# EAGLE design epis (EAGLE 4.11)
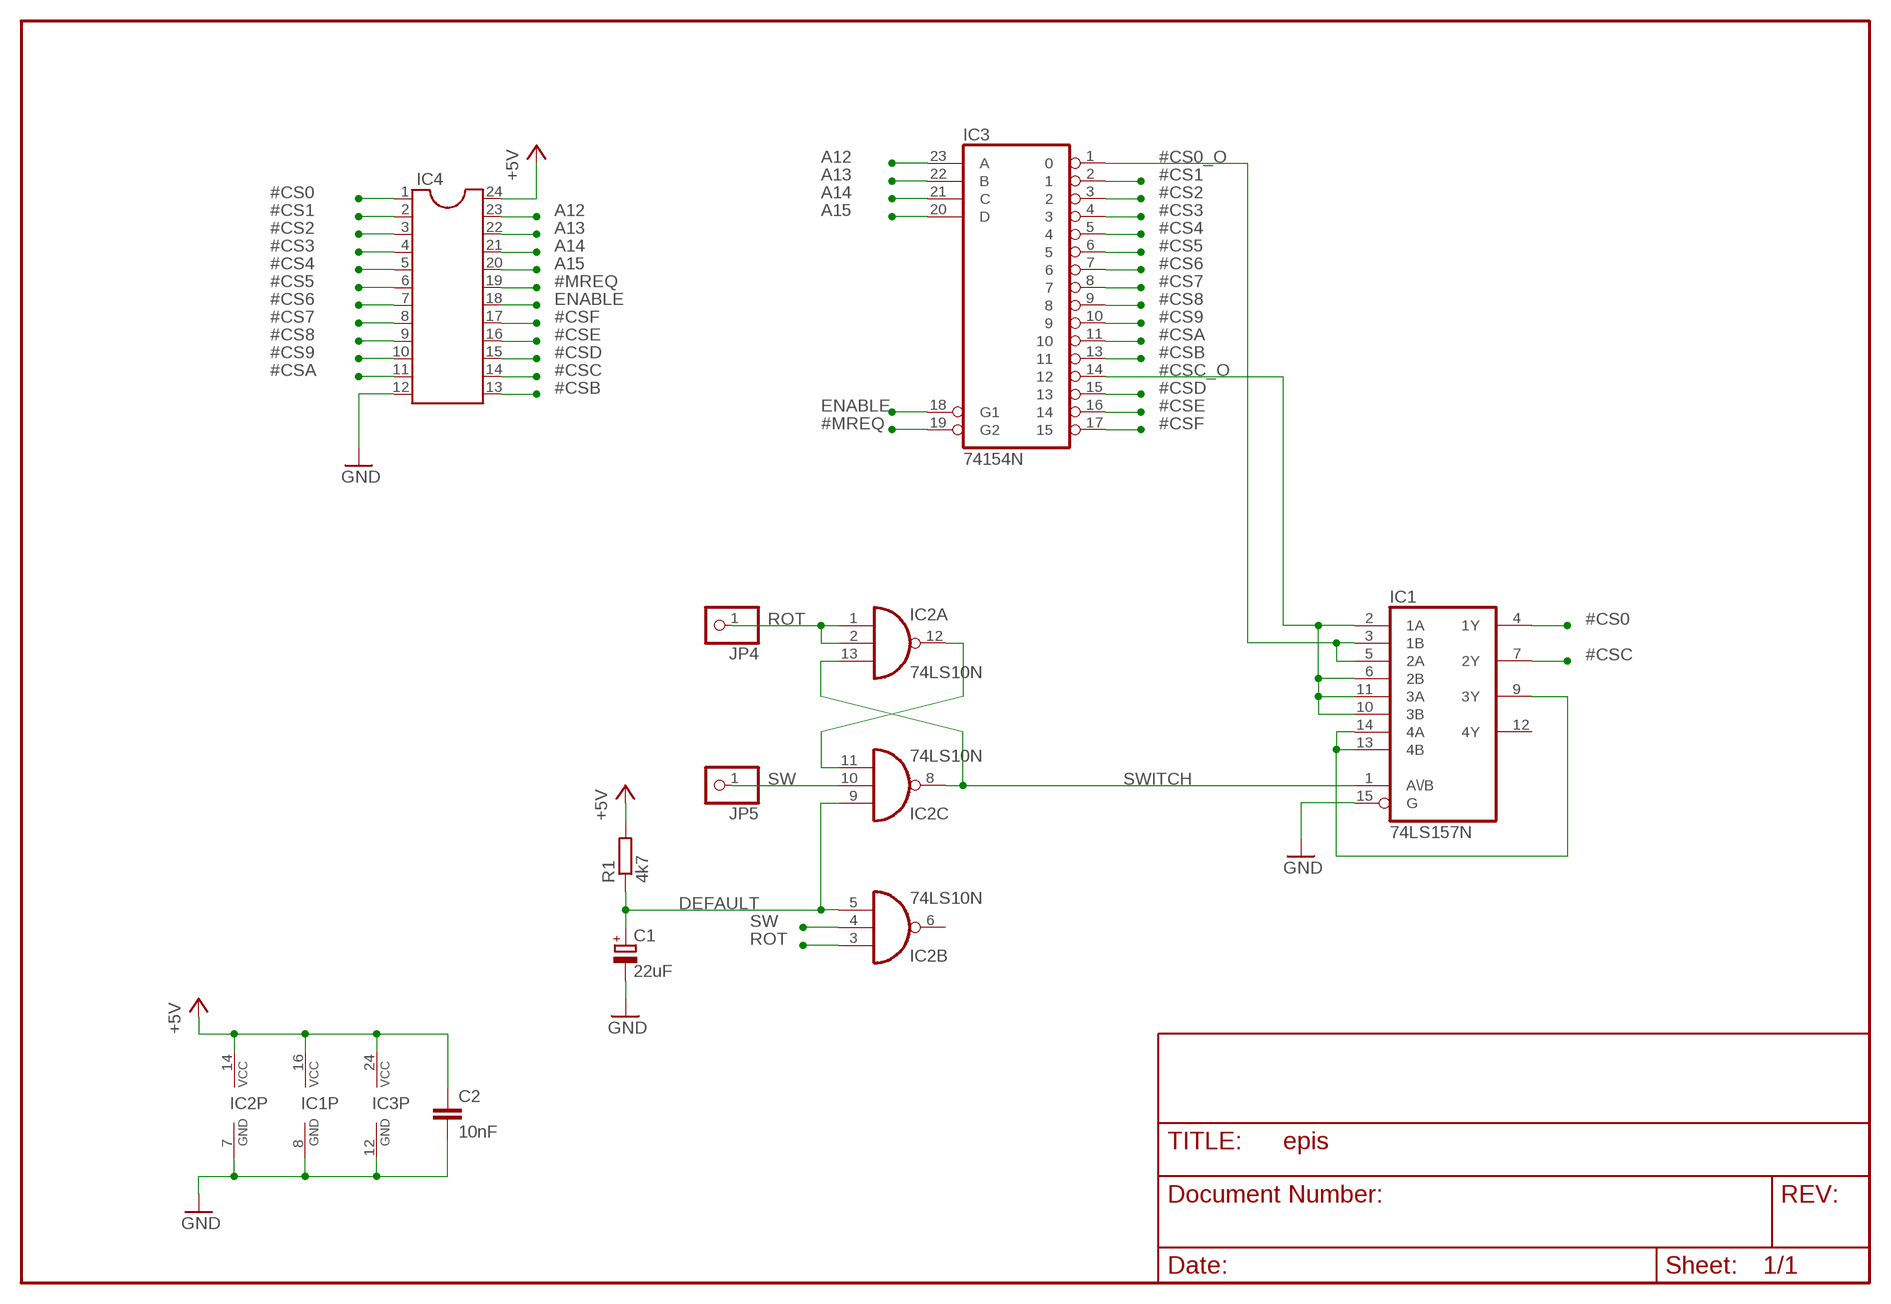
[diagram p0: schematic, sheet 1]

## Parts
C1  22uF  CPOL-EUE5-5  [E5-5]
C2  10nF  C-EU050-024X044  [C050-024X044]
IC1  74LS157N  [DIL16]
IC2  74LS10N  [DIL14]
IC3  74154N  [DIL24-6]
IC4  DIL24-6  [DIL24-6]
JP4  PINHD-1X1  [1X01]
JP5  PINHD-1X1  [1X01]
R1  4k7  R-EU_0309/10  [0309/10]

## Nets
#CS0: IC1.4(1Y) IC4.1
#CS0_O: IC1.3(1B) IC1.5(2A) IC3.1
#CS1: IC3.2 IC4.2
#CS2: IC3.3 IC4.3
#CS3: IC3.4 IC4.4
#CS4: IC3.5 IC4.5
#CS5: IC3.6 IC4.6
#CS6: IC3.7 IC4.7
#CS7: IC3.8 IC4.8
#CS8: IC3.9 IC4.9
#CS9: IC3.10 IC4.10
#CSA: IC3.11 IC4.11
#CSB: IC3.13 IC4.13
#CSC: IC1.7(2Y) IC4.14
#CSC_O: IC1.2(1A) IC1.6(2B) IC1.10(3B) IC1.11(3A) IC3.14
#CSD: IC3.15 IC4.15
#CSE: IC3.16 IC4.16
#CSF: IC3.17 IC4.17
#MREQ: IC3.19(G2) IC4.19
+5V: C2.1 IC1.16(VCC) IC2.14(P:VCC) IC3.24(VCC) IC4.24 R1.2
A12: IC3.23(A) IC4.23
A13: IC3.22(B) IC4.22
A14: IC3.21(C) IC4.21
A15: IC3.20(D) IC4.20
DEFAULT: C1.+ IC2.5(B:I2) IC2.9(C:I0) R1.1
ENABLE: IC3.18(G1) IC4.18
GND: C1.- C2.2 IC1.8(GND) IC1.15(G) IC2.7(P:GND) IC3.12(GND) IC4.12
N$2: IC1.9(3Y) IC1.13(4B) IC1.14(4A)
N$5: IC2.11(C:I2) IC2.12(A:O)
ROT: IC2.1(A:I0) IC2.2(A:I1) IC2.3(B:I0) JP4.1
SW: IC2.4(B:I1) IC2.10(C:I1) JP5.1
SWITCH: IC1.1(A\/B) IC2.8(C:O) IC2.13(A:I2)
Unconnected: IC1.12(4Y) IC2.6(B:O)

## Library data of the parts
C1 = rcl:CPOL-EU: POLARIZED CAPACITOR, European symbol
C2 = rcl:C-EU: CAPACITOR, European symbol
IC1 = 74xx-eu:74*157: Quadruple 2-line to 1-line data SELECTOR/MULTIPLEXER
IC2 = 74xx-eu:74*10: Triple 3-input NAND gate
IC3 = 74xx-eu:74*154: 4-line to 16-line data SELECTOR/MULTIPLEXER
IC4 = ic-package:DIL24: Dual In Line
JP4 JP5 = pinhead:PINHD-1X1: PIN HEADER
R1 = rcl:R-EU_: RESISTOR, European symbol

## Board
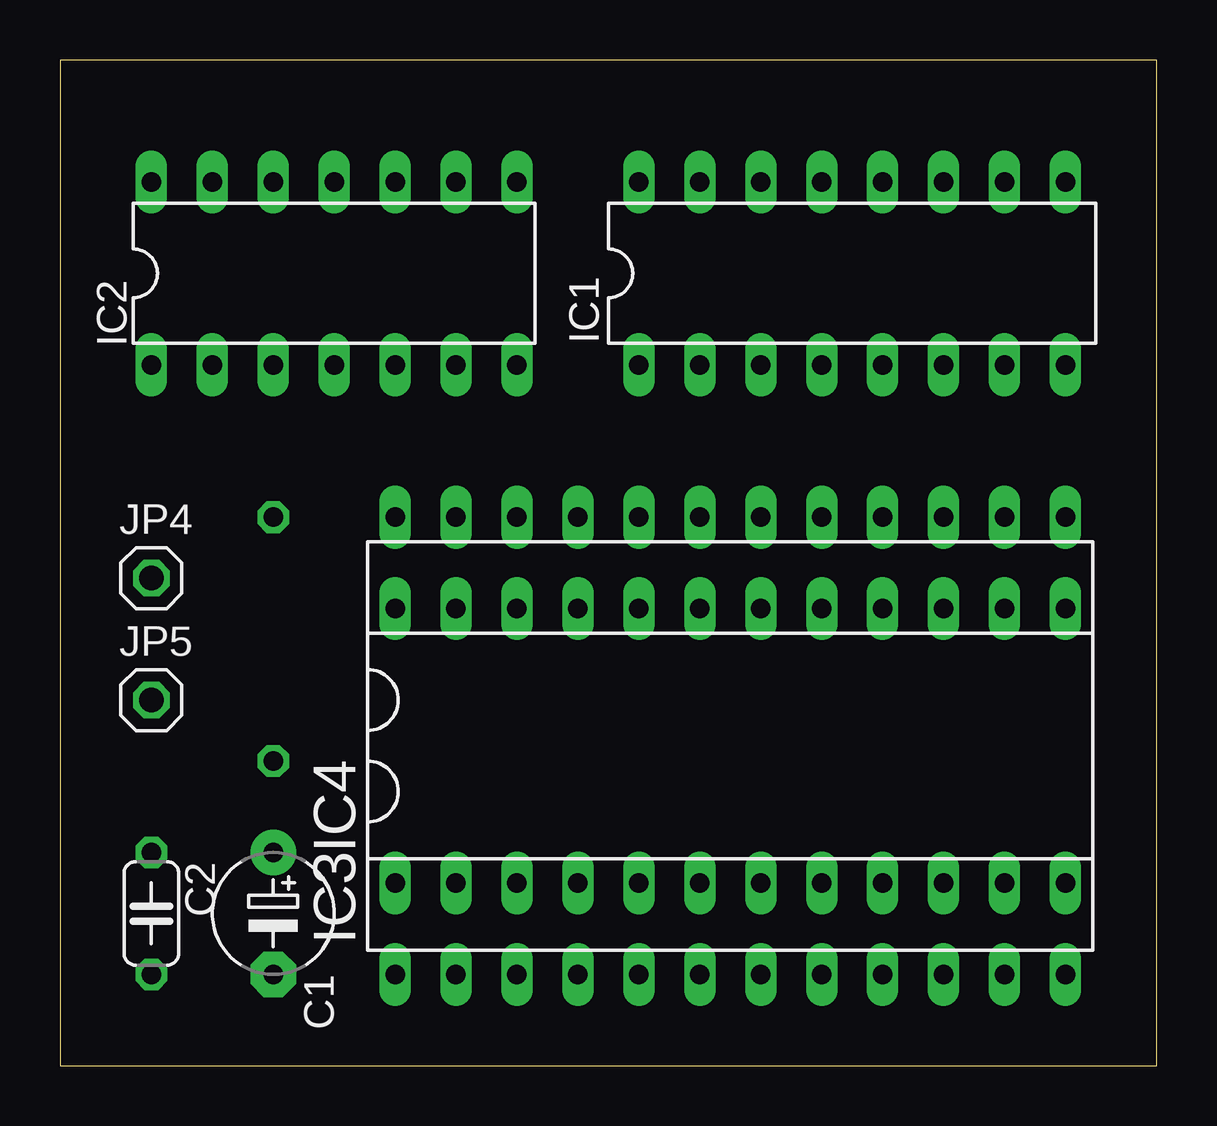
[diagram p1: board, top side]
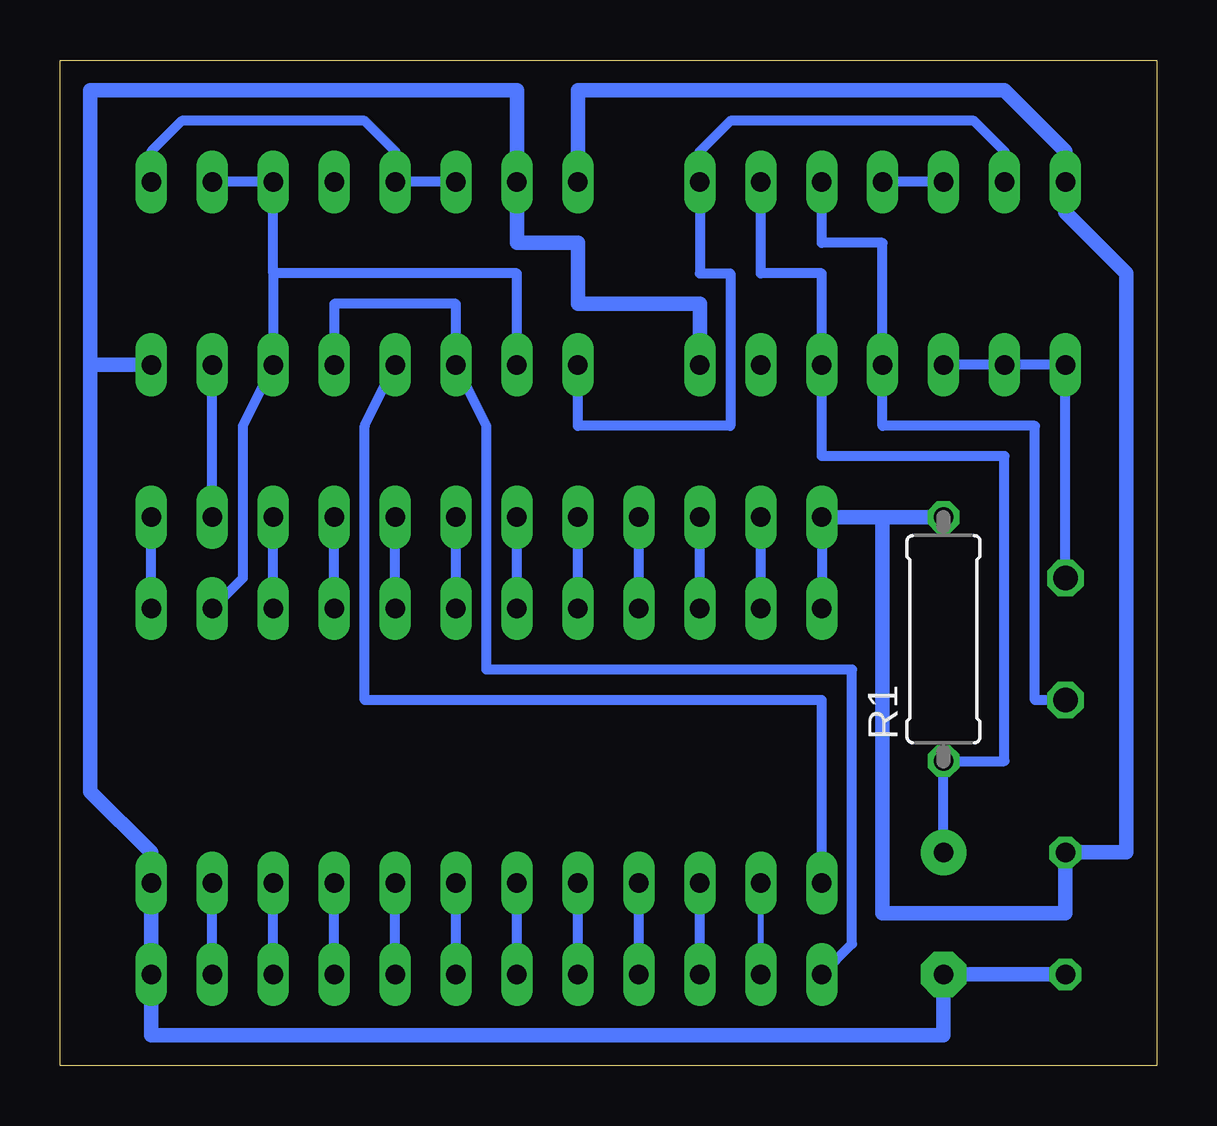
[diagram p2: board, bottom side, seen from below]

Size 45.72 x 41.91 mm. Coordinates in mm from the lower left corner, seen from the top.
Outline: 0,0 45.72,0 45.72,41.91 0,41.91 0,0
Copper layers (1*16): Top 0.035mm / dielectric 1.5mm / Bottom 0.035mm
Design rules "default": minimum track width 10mil, minimum drill 0.4mm, track to track 8mil, track to pad 8mil, pad to pad 8mil, via to via 8mil, smd to smd 8mil, copper to edge 20mil, drill to drill 8mil, minimum pad ring 10mil, minimum via ring 8mil, stop-mask expansion 4mil, vias tented up to drill 0mil, thermal gap 10mil

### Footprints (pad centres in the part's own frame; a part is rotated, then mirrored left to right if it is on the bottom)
E5-5 = drill 0.813 pad 1.905 round: + -2.54,0 | drill 0.813 pad 1.905 octagon: - 2.54,0
C050-024X044 = drill 0.813 octagon: 1 -2.54,0; 2 2.54,0
DIL16 = drill 0.813 long: 1 -8.89,-3.81; 2 -6.35,-3.81; 3 -3.81,-3.81; 4 -1.27,-3.81; 5 1.27,-3.81; 6 3.81,-3.81; 7 6.35,-3.81; 8 8.89,-3.81; 9 8.89,3.81; 10 6.35,3.81; 11 3.81,3.81; 12 1.27,3.81; 13 -1.27,3.81; 14 -3.81,3.81; 15 -6.35,3.81; 16 -8.89,3.81
DIL14 = drill 0.813 long: 1 -7.62,-3.81; 2 -5.08,-3.81; 3 -2.54,-3.81; 4 0,-3.81; 5 2.54,-3.81; 6 5.08,-3.81; 7 7.62,-3.81; 8 7.62,3.81; 9 5.08,3.81; 10 2.54,3.81; 11 0,3.81; 12 -2.54,3.81; 13 -5.08,3.81; 14 -7.62,3.81
DIL24-6 = drill 0.813 long: 1 -13.97,-7.62; 2 -11.43,-7.62; 3 -8.89,-7.62; 4 -6.35,-7.62; 5 -3.81,-7.62; 6 -1.27,-7.62; 7 1.27,-7.62; 8 3.81,-7.62; 9 6.35,-7.62; 10 8.89,-7.62; 11 11.43,-7.62; 12 13.97,-7.62; 13 13.97,7.62; 14 11.43,7.62; 15 8.89,7.62; 16 6.35,7.62; 17 3.81,7.62; 18 1.27,7.62; 19 -1.27,7.62; 20 -3.81,7.62; 21 -6.35,7.62; 22 -8.89,7.62; 23 -11.43,7.62; 24 -13.97,7.62
1X01 = drill 1.016 octagon: 1 0,0
0309/10 = drill 0.813 octagon: 1 -5.08,0; 2 5.08,0

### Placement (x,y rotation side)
C1  8.89,6.35 270 top
C2  3.81,6.35 270 top
IC1  33.02,33.02 0 top
IC2  11.43,33.02 0 top
IC3  27.94,11.43 0 top
IC4  27.94,15.24 0 top
JP4  3.81,20.32 0 top
JP5  3.81,15.24 0 top
R1  8.89,17.78 90 bottom

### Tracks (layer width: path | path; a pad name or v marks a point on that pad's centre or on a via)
#CS0
  Bottom 0.406: IC4.1 13.97,15.24 33.02,15.24 33.02,26.67 IC1.4
#CS0_O
  Bottom 0.406: IC1.5 34.29,31.75 29.21,31.75 IC1.3 27.94,26.67 27.94,16.51 12.7,16.51 12.7,5.08 IC3.1
#CS1
  Bottom 0.254: IC3.2 IC4.2
#CS2
  Bottom 0.406: IC3.3 IC4.3
#CS3
  Bottom 0.406: IC3.4 IC4.4
#CS4
  Bottom 0.406: IC3.5 IC4.5
#CS5
  Bottom 0.406: IC3.6 IC4.6
#CS6
  Bottom 0.406: IC3.7 IC4.7
#CS7
  Bottom 0.406: IC3.8 IC4.8
#CS8
  Bottom 0.406: IC3.9 IC4.9
#CS9
  Bottom 0.406: IC3.10 IC4.10
#CSA
  Bottom 0.406: IC3.11 IC4.11
#CSB
  Bottom 0.406: IC3.13 IC4.13
#CSC
  Bottom 0.406: IC4.14 IC1.7
#CSC_O
  Bottom 0.406: IC1.10 IC1.11 36.83,33.02 | 36.83,33.02 IC1.6 38.1,26.67 38.1,20.32 IC3.14 | 36.83,33.02 26.67,33.02 IC1.2
#CSD
  Bottom 0.406: IC3.15 IC4.15
#CSE
  Bottom 0.406: IC3.16 IC4.16
#CSF
  Bottom 0.406: IC3.17 IC4.17
#MREQ
  Bottom 0.406: IC3.19 IC4.19
+5V
  Bottom 0.406: IC4.24 IC3.24
  Bottom 0.61: IC1.16 24.13,40.64 6.35,40.64 3.81,38.1 IC2.14 3.81,35.56 1.27,33.02 1.27,8.89 C2.1 3.81,6.35 11.43,6.35 11.43,22.86 | 11.43,22.86 IC4.24 | 11.43,22.86 R1.2
A12
  Bottom 0.406: IC3.23 IC4.23
A13
  Bottom 0.406: IC3.22 IC4.22
A14
  Bottom 0.406: IC3.21 IC4.21
A15
  Bottom 0.406: IC3.20 IC4.20
DEFAULT
  Bottom 0.406: C1.+ R1.1 6.35,12.7 6.35,25.4 13.97,25.4 IC2.5 13.97,33.02 16.51,33.02 IC2.9
ENABLE
  Bottom 0.406: IC3.18 IC4.18
GND
  Bottom 0.61: 44.45,29.21 44.45,40.64 26.67,40.64 IC1.15 26.67,34.29 24.13,34.29 24.13,31.75 19.05,31.75 IC2.7 | 44.45,29.21 IC1.8 | 44.45,29.21 44.45,11.43 41.91,8.89 IC4.12 IC3.12 41.91,1.27 8.89,1.27 C1.- C2.2
N$2
  Bottom 0.406: IC1.14 IC1.13 31.75,38.1 33.02,39.37 40.64,39.37 41.91,38.1 IC1.9
N$5
  Bottom 0.406: IC2.12 IC2.11
ROT
  Bottom 0.406: JP4.1 IC2.1 IC2.2 IC2.3
SW
  Bottom 0.406: JP5.1 5.08,15.24 5.08,26.67 11.43,26.67 IC2.4 11.43,34.29 13.97,34.29 IC2.10
SWITCH
  Bottom 0.406: IC2.13 6.35,38.1 7.62,39.37 17.78,39.37 19.05,38.1 IC2.8 19.05,33.02 17.78,33.02 17.78,26.67 24.13,26.67 IC1.1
